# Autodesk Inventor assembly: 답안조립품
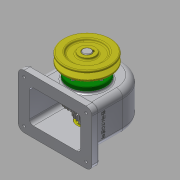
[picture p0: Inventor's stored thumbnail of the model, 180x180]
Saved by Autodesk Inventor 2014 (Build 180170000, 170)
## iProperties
Created: 2016-10
Part Number: 답안조립품
Document SubType Name: Assembly
Designer: SCD-A13
Author: SCD-A13
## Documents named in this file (15)
- C:\Users\SCD-A13\Desktop\461008V1029\461008V1029\답안조립품.iam
- C:\Users\SCD-A13\Desktop\461008V1029\461008V1029\본체.ipt
- C:\Users\SCD-A13\Desktop\461008V1029\461008V1029\V-벨트풀리.ipt
- C:\Users\SCD-A13\Desktop\461008V1029\461008V1029\뒤커버.ipt
- C:\Users\SCD-A13\Desktop\461008V1029\461008V1029\멈춤나사 - M4x10.ipt
- C:\Users\SCD-A13\Desktop\461008V1029\461008V1029\베어링 6203.ipt
- C:\Users\SCD-A13\Desktop\461008V1029\461008V1029\볼트 M3 x 8.ipt
- C:\Users\SCD-A13\Desktop\461008V1029\461008V1029\볼트 M3 x 10.ipt
- C:\Users\SCD-A13\Desktop\461008V1029\461008V1029\부시.ipt
- C:\Users\SCD-A13\Desktop\461008V1029\461008V1029\스퍼기어.ipt
- C:\Users\SCD-A13\Desktop\461008V1029\461008V1029\앞커버.ipt
- C:\Users\SCD-A13\Desktop\461008V1029\461008V1029\오일씰 28 40 8.ipt
- C:\Users\SCD-A13\Desktop\461008V1029\461008V1029\축.ipt
- C:\Users\SCD-A13\Desktop\461008V1029\461008V1029\키 - 5 x 5 x 18.ipt
- C:\Users\SCD-A13\Desktop\461008V1029\461008V1029\키 - 6 x 6 x 22.ipt
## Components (9 placed, 3 different names)
1. V-벨트풀리:1
2. ISO 4762 M3 x 8:1 — 강체:6
3. ISO 4762 M3 x 10:1 — 강체:10
4. ISO 4762 M3 x 8:2 — 강체:7
5. ISO 4762 M3 x 8:3 — 강체:8
6. ISO 4762 M3 x 8:4 — 강체:9
7. ISO 4762 M3 x 10:2 — 강체:11
8. ISO 4762 M3 x 10:3 — 강체:12
9. ISO 4762 M3 x 10:4 — 강체:13
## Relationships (8: WeldJoint 8)
- 강체:6 [WeldJoint]: ISO 4762 M3 x 8:1
- 강체:7 [WeldJoint]: ISO 4762 M3 x 8:2
- 강체:8 [WeldJoint]: ISO 4762 M3 x 8:3
- 강체:9 [WeldJoint]: ISO 4762 M3 x 8:4
- 강체:10 [WeldJoint]: ISO 4762 M3 x 10:1
- 강체:11 [WeldJoint]: ISO 4762 M3 x 10:2
- 강체:12 [WeldJoint]: ISO 4762 M3 x 10:3
- 강체:13 [WeldJoint]: ISO 4762 M3 x 10:4
